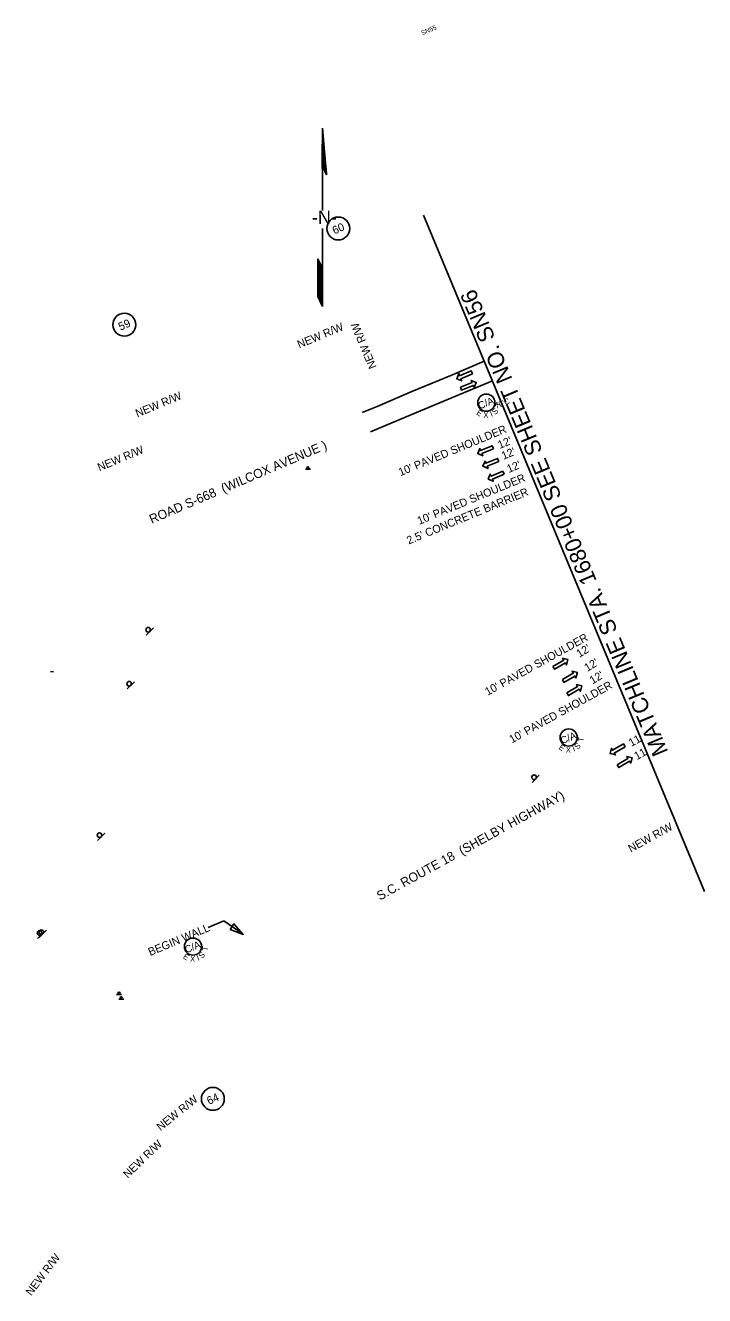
# Model space of a CAD drawing. Extents: x 1813391 to 1815007, y 1189909 to 1191222.
# Drawn here: x 1814412 to 1815007, y 1190111 to 1191222 of the extents above; entities that cross this region are included whole.
import ezdxf

# ---------------------------------------------------------------- set-up
doc = ezdxf.new("R2010")
doc.units = 0
for name, color, linetype in [('RD_EX_DV_Prop_txCode', 7, 'Continuous'), ('RD_EX_DV_TX_Prop', 7, 'Continuous'), ('RD_EX_Road', 7, 'Continuous'), ('RD_PD_Final_LnLine', 7, 'Continuous'), ('RD_PD_Final_TX', 7, 'Continuous'), ('RD_PD_RW_TX', 7, 'Continuous'), ('RD_PD_TX_CstnLmt', 7, 'Continuous'), ('RD_PD_WallFill', 7, 'Continuous'), ('RD_SHT_MatchLine', 7, 'Continuous'), ('RD_SHT_TX', 7, 'Continuous'), ('RD_Sketch1', 7, 'Continuous'), ('RD_Sketch8', 7, 'Continuous'), ('RD_TX_RoadID', 7, 'Continuous'), ('SN_P_Signs', 7, 'Continuous'), ('TERMINATOR', 7, 'Continuous')]:
    doc.layers.add(name, color=color, linetype=linetype)

# ---------------------------------------------------------------- blocks, each defined once
blk = doc.blocks.new('SARRW2')
at = {"layer": 'RD_PD_Final_LnLine'}
blk.add_lwpolyline([(-12, 1.2), (-12, -1.2), (-2.83, -1.2), (-2.83, -2.83), (0, 0), (-2.83, 2.83), (-2.83, 1.2)], close=True, dxfattribs=at)

msp = doc.modelspace()

# ---------------------------------------------------------------- linework, layer by layer
at = {"layer": 'RD_EX_DV_TX_Prop'}
for centre in [(1814686.1, 1191044.1), (1814499, 1190959.9), (1814576.4, 1190282.8)]:
    msp.add_circle(centre, 10, dxfattribs=at)
at = {"layer": 'RD_EX_Road'}
for points in [[(1814707, 1190883.2), (1814720, 1190888.5), (1814750.6, 1190901.5), (1814785.9, 1190916.1), (1814813.8, 1190928)], [(1814821, 1190910.7), (1814770.7, 1190889.9), (1814727.3, 1190871.7), (1814714.2, 1190866.1)]]:
    msp.add_lwpolyline(points, dxfattribs=at)
at = {"layer": 'RD_PD_Final_TX'}
for q in [(1814572.2, 1190432.8), (1814602, 1190427.5)]:
    msp.add_line((1814585.9, 1190438.6), q, dxfattribs=at)
at = {"layer": 'RD_PD_WallFill'}
msp.add_line((1814434.5, 1190656.7), (1814437, 1190656.3), dxfattribs=at)
at = {"layer": 'RD_SHT_MatchLine'}
msp.add_line((1814760.7, 1191055.8), (1815006.6, 1190464.1), dxfattribs=at)
at = {"layer": 'RD_Sketch1'}
for p, q in [((1814672.2, 1191131.8), (1814672, 1191096.7)), ((1814675.9, 1191091.1), (1814672.2, 1191131.8)), ((1814672.2, 1191097), (1814672.2, 1191075.1)), ((1814672.5, 1191098.1), (1814675.9, 1191091.1)), ((1814672.2, 1191075.1), (1814672.2, 1191059.7)), ((1814672.2, 1191044.2), (1814672.2, 1191018.5)), ((1814668.2, 1191003.4), (1814668.2, 1191017.6)), ((1814668.2, 1191017.6), (1814672.2, 1191009)), ((1814672.2, 1191018.5), (1814672.2, 1190975.9)), ((1814668.2, 1190984.5), (1814668.2, 1191003.4)), ((1814672.2, 1190975.9), (1814668.2, 1190984.5))]:
    msp.add_line(p, q, dxfattribs=at)
for points in [[(1814672.2, 1191097.3), (1814672.2, 1191131.7)], [(1814672.3, 1191097.5), (1814672.3, 1191130.7)], [(1814672.4, 1191097.8), (1814672.4, 1191129.7)], [(1814672.5, 1191098.1), (1814672.5, 1191128.6)], [(1814672.6, 1191097.9), (1814672.6, 1191127.6)], [(1814672.7, 1191097.7), (1814672.7, 1191126.6)], [(1814672.8, 1191097.5), (1814672.8, 1191125.5)], [(1814672.8, 1191097.3), (1814672.8, 1191124.5)], [(1814672.9, 1191097.1), (1814672.9, 1191123.5)], [(1814673, 1191096.9), (1814673, 1191122.4)], [(1814672.1, 1191097), (1814672.1, 1191117.8)], [(1814673.1, 1191096.8), (1814673.1, 1191121.4)], [(1814673.2, 1191096.6), (1814673.2, 1191120.4)], [(1814673.3, 1191096.4), (1814673.3, 1191119.3)], [(1814673.4, 1191096.2), (1814673.4, 1191118.3)], [(1814673.5, 1191096), (1814673.5, 1191117.3)], [(1814673.6, 1191095.8), (1814673.6, 1191116.2)], [(1814673.7, 1191095.6), (1814673.7, 1191115.2)], [(1814673.8, 1191095.4), (1814673.8, 1191114.2)], [(1814673.9, 1191095.2), (1814673.9, 1191113.1)], [(1814674, 1191095), (1814674, 1191112.1)], [(1814674.1, 1191094.8), (1814674.1, 1191111.1)], [(1814672, 1191096.8), (1814672, 1191101.9)], [(1814674.2, 1191094.6), (1814674.2, 1191110)], [(1814674.3, 1191094.5), (1814674.3, 1191109)], [(1814674.4, 1191094.3), (1814674.4, 1191108)], [(1814674.5, 1191094.1), (1814674.5, 1191106.9)], [(1814674.5, 1191093.9), (1814674.5, 1191105.9)], [(1814674.6, 1191093.7), (1814674.6, 1191104.9)], [(1814674.7, 1191093.5), (1814674.7, 1191103.8)], [(1814674.8, 1191093.3), (1814674.8, 1191102.8)], [(1814674.9, 1191093.1), (1814674.9, 1191101.8)], [(1814675, 1191092.9), (1814675, 1191100.7)], [(1814675.1, 1191092.7), (1814675.1, 1191099.7)], [(1814675.2, 1191092.5), (1814675.2, 1191098.7)], [(1814675.3, 1191092.3), (1814675.3, 1191097.6)], [(1814675.4, 1191092.2), (1814675.4, 1191096.6)], [(1814675.5, 1191092), (1814675.5, 1191095.6)], [(1814675.6, 1191091.8), (1814675.6, 1191094.5)], [(1814675.7, 1191091.6), (1814675.7, 1191093.5)], [(1814675.8, 1191091.4), (1814675.8, 1191092.5)], [(1814675.9, 1191091.2), (1814675.9, 1191091.5)], [(1814668.3, 1190984.3), (1814668.3, 1191017.4)], [(1814668.4, 1190984.1), (1814668.4, 1191017.2)], [(1814668.4, 1190983.9), (1814668.4, 1191017)], [(1814668.5, 1190983.7), (1814668.5, 1191016.8)], [(1814668.6, 1190983.5), (1814668.6, 1191016.6)], [(1814668.7, 1190983.3), (1814668.7, 1191016.4)], [(1814668.8, 1190983.1), (1814668.8, 1191016.2)], [(1814668.9, 1190982.9), (1814668.9, 1191016)], [(1814669, 1190982.7), (1814669, 1191015.8)], [(1814669.1, 1190982.5), (1814669.1, 1191015.6)], [(1814669.2, 1190982.3), (1814669.2, 1191015.4)], [(1814669.3, 1190982.1), (1814669.3, 1191015.2)], [(1814669.4, 1190981.9), (1814669.4, 1191015)], [(1814669.5, 1190981.7), (1814669.5, 1191014.8)], [(1814669.6, 1190981.5), (1814669.6, 1191014.6)], [(1814669.7, 1190981.3), (1814669.7, 1191014.4)], [(1814669.8, 1190981.1), (1814669.8, 1191014.2)], [(1814669.9, 1190980.9), (1814669.9, 1191014)], [(1814670, 1190980.7), (1814670, 1191013.8)], [(1814670.1, 1190980.5), (1814670.1, 1191013.6)], [(1814670.1, 1190980.3), (1814670.1, 1191013.4)], [(1814670.2, 1190980.1), (1814670.2, 1191013.1)], [(1814670.3, 1190979.9), (1814670.3, 1191012.9)], [(1814670.4, 1190979.7), (1814670.4, 1191012.7)], [(1814670.5, 1190979.5), (1814670.5, 1191012.5)], [(1814670.6, 1190979.3), (1814670.6, 1191012.3)], [(1814670.7, 1190979.1), (1814670.7, 1191012.1)], [(1814670.8, 1190978.9), (1814670.8, 1191011.9)], [(1814670.9, 1190978.7), (1814670.9, 1191011.7)], [(1814671, 1190978.5), (1814671, 1191011.5)], [(1814671.1, 1190978.3), (1814671.1, 1191011.3)], [(1814671.2, 1190978.1), (1814671.2, 1191011.1)], [(1814671.3, 1190977.8), (1814671.3, 1191010.9)], [(1814671.4, 1190977.6), (1814671.4, 1191010.7)], [(1814671.5, 1190977.4), (1814671.5, 1191010.5)], [(1814671.6, 1190977.2), (1814671.6, 1191010.3)], [(1814671.7, 1190977), (1814671.7, 1191010.1)], [(1814671.8, 1190976.8), (1814671.8, 1191009.9)], [(1814671.8, 1190976.6), (1814671.8, 1191009.7)], [(1814671.9, 1190976.4), (1814671.9, 1191009.5)], [(1814672, 1190976.2), (1814672, 1191009.3)], [(1814672.1, 1190976), (1814672.1, 1191009.1)]]:
    msp.add_lwpolyline(points, dxfattribs=at)
at = {"layer": 'RD_Sketch8'}
for centre in [(1814815.6, 1190891.7), (1814887.7, 1190598.9), (1814559, 1190416)]:
    msp.add_circle(centre, 7.5, dxfattribs=at)
at = {"layer": 'SN_P_Signs'}
for p, q in [((1814657.3, 1190833.7), (1814661.8, 1190833.7)), ((1814518.1, 1190688.5), (1814524.4, 1190694.9)), ((1814501.4, 1190641.3), (1814507.8, 1190647.6)), ((1814855.7, 1190559.4), (1814862, 1190565.8)), ((1814475.4, 1190508.8), (1814481.8, 1190515.2)), ((1814423, 1190423.2), (1814429.3, 1190429.6)), ((1814424.5, 1190424), (1814430.9, 1190430.3)), ((1814492.1, 1190374.1), (1814496.6, 1190374.1)), ((1814494, 1190370), (1814498.5, 1190370))]:
    msp.add_line(p, q, dxfattribs=at)
for centre, radius in [((1814659.5, 1190834.7), 1), ((1814519.8, 1190693.1), 2), ((1814503.2, 1190645.9), 2), ((1814857.4, 1190564.1), 2), ((1814477.2, 1190513.4), 2), ((1814424.7, 1190427.9), 2), ((1814426.3, 1190428.6), 2), ((1814494.4, 1190375.1), 1), ((1814496.2, 1190371), 1)]:
    msp.add_circle(centre, radius, dxfattribs=at)
at = {"layer": 'TERMINATOR'}
msp.add_lwpolyline([(1814591.4, 1190430.9), (1814603, 1190426.6), (1814594.8, 1190435.9)], close=True, dxfattribs=at)

# ---------------------------------------------------------------- block references
at = {"layer": 'RD_PD_Final_LnLine'}
for p, xscale, yscale, rotation in [((1814789.7, 1190912.7), 1.2000000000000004, 1.2000000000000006, -157.44760385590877), ((1814806.8, 1190909.4), 1.2000000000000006, 1.200000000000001, 22.55239614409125), ((1814808.1, 1190847.2), 1.2000000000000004, 1.2000000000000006, -157.44760385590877), ((1814812.7, 1190836.1), 1.2000000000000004, 1.2000000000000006, -157.44760385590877), ((1814817.3, 1190824.9), 1.2000000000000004, 1.2000000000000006, -157.44760385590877), ((1814887, 1190667), 1.1999999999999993, 1.1999999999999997, 30.219987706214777), ((1814895.3, 1190655.6), 1.1999999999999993, 1.1999999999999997, 30.219987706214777), ((1814899.2, 1190644), 1.1999999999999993, 1.1999999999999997, 30.219987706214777), ((1814923.9, 1190584.8), 1.1999999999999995, 1.2, -149.78001229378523), ((1814943.2, 1190581.1), 1.1999999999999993, 1.1999999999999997, 30.219987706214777)]:
    msp.add_blockref('SARRW2', p, dxfattribs=dict(at, xscale=xscale, yscale=yscale, rotation=rotation))

# ---------------------------------------------------------------- texts
at = {"layer": 'RD_EX_DV_Prop_txCode'}
for s, p in [('60', (1814682.8, 1191038.8)), ('59', (1814495.6, 1190954.6)), ('64', (1814573, 1190277.5))]:
    msp.add_text(s, height=7, rotation=23.7538, dxfattribs=at).set_placement(p)
at = {"layer": 'RD_PD_Final_TX'}
for s, rotation, p in [("10' PAVED SHOULDER", 22.4268, (1814740.5, 1190827.4)), ("12'", 22.759, (1814827.4, 1190851.2)), ("12'", 22.759, (1814830.6, 1190841.7)), ("12'", 22.759, (1814835.3, 1190830.2)), ("10' PAVED SHOULDER", 22.4268, (1814757, 1190784.8)), ("2.5' CONCRETE BARRIER", 22.4268, (1814747.7, 1190767.6)), ("10' PAVED SHOULDER", 28.9296, (1814816.8, 1190635.3)), ("12'", 31.3888, (1814897, 1190668.5)), ("12'", 31.3888, (1814904, 1190656.2)), ("12'", 31.3888, (1814908.6, 1190645.2)), ("10' PAVED SHOULDER", 28.9296, (1814838, 1190593.6)), ("11'", 28.9968, (1814942.5, 1190590.6)), ("11'", 28.9968, (1814947.3, 1190579)), ('BEGIN WALL', 22.8166, (1814521.6, 1190407.7))]:
    msp.add_text(s, height=7, rotation=rotation, dxfattribs=at).set_placement(p)
at = {"layer": 'RD_PD_RW_TX'}
for rotation, p in [(22.5666, (1814652, 1190939.1)), (112.5666, (1814719.8, 1190923.1)), (22.5666, (1814510.4, 1190878.8)), (22.5666, (1814477.2, 1190831.6)), (28.9531, (1814942.1, 1190498.1)), (38.6623, (1814530.6, 1190254.5)), (43.7566, (1814501.9, 1190213)), (52.6995, (1814417.5, 1190110.1))]:
    msp.add_text('NEW R/W', height=7, rotation=rotation, dxfattribs=at).set_placement(p)
at = {"layer": 'RD_PD_TX_CstnLmt'}
msp.add_text("70'C", height=5, rotation=22.5666, dxfattribs=at).set_placement((1814824.2, 1190886.2))
at = {"layer": 'RD_SHT_TX'}
for s, height, rotation, p in [('SN55', 4, 22.5666, (1814759.7, 1191213.1)), ('MATCHLINE STA. 1680+00 SEE SHEET NO. SN56', 14.173, 112.6789, (1814975, 1190586.3))]:
    msp.add_text(s, height=height, rotation=rotation, dxfattribs=at).set_placement(p)
at = {"layer": 'RD_Sketch1'}
msp.add_text('-N-', height=11.81, rotation=360, dxfattribs=at).set_placement((1814663, 1191047.9))
at = {"layer": 'RD_Sketch8'}
for s, height, rotation, p in [('C/A', 6.25, 22.5666, (1814810, 1190885.8)), ('T', 5, 80.7517, (1814828.4, 1190887.6)), ('E', 5, 325.7778, (1814806.5, 1190881.9)), ('X', 5, 358.2072, (1814813, 1190878.5)), ('I', 5, 22.3672, (1814820.1, 1190879.2)), ('S', 5, 44.359, (1814823.4, 1190880.8)), ('C/A', 6.25, 22.5666, (1814882.1, 1190593)), ('E', 5, 325.7778, (1814878.5, 1190589.1)), ('X', 5, 358.2072, (1814885.1, 1190585.7)), ('I', 5, 22.3672, (1814892.2, 1190586.4)), ('S', 5, 44.359, (1814895.5, 1190588)), ('T', 5, 80.7517, (1814900.5, 1190594.8)), ('C/A', 6.25, 22.5666, (1814553.4, 1190410.1)), ('S', 5, 44.359, (1814566.8, 1190405.1)), ('T', 5, 80.7517, (1814571.7, 1190411.8)), ('E', 5, 325.7778, (1814549.8, 1190406.2)), ('X', 5, 358.2072, (1814556.4, 1190402.8)), ('I', 5, 22.3672, (1814563.5, 1190403.5))]:
    msp.add_text(s, height=height, rotation=rotation, dxfattribs=at).set_placement(p)
at = {"layer": 'RD_TX_RoadID'}
for s, rotation, p in [('ROAD S-668  (WILCOX AVENUE )', 23.1616, (1814522.9, 1190785.7)), ('S.C. ROUTE 18  (SHELBY HIGHWAY)', 28.8878, (1814722.5, 1190456.1))]:
    msp.add_text(s, height=8, rotation=rotation, dxfattribs=at).set_placement(p)

doc.saveas('drawing.dxf')
